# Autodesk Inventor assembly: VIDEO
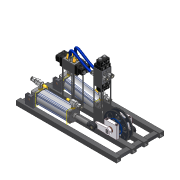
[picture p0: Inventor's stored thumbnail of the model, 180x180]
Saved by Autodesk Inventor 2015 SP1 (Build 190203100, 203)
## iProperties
Created: 2015-05
Part Number: VIDEO
Document SubType Name: Assembly
Designer: TREINA11
Author: TREINA11
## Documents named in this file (2)
- C:\Users\TREINA11\Desktop\#01- Polymechanics and Automation\01 - 3D Models\Pneumatic System\VIDEO.iam
- C:\Users\TREINA11\Desktop\#01- Polymechanics and Automation\01 - 3D Models\Pneumatic System\Teljes hajtás (Video).iam
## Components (1 placed, 1 different names)
1. Teljes hajtás (Video):1 [sub-assembly] — Mate:1, Flush:1, Flush:2
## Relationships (3: Flush 2, Mate 1)
- Mate:1: Teljes hajtás (Video):1
- Flush:1: Teljes hajtás (Video):1
- Flush:2: Teljes hajtás (Video):1
